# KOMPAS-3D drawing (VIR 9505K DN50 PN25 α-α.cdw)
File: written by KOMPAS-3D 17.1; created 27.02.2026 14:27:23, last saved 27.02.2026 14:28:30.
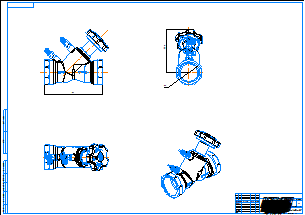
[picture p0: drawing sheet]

Sheet 1: A1, landscape

Title block, sheet 1: name: VIR 9505K DN50 / PN25 р-р; material: Внимание! Данный продукт является объектом авторского права ООО «Торговый Дом АДЛ». / Запрещается изменение, копирование, распространение / (в том числе путем копирования на другие сайты и ресурсы в Интернете) / или любое иное использование информации и объектов без предварительного / согласия правообладателя (ООО «Торговый Дом АДЛ»).; sheets: 1; organisation: ООО "Торговый дом АДЛ"; sheet format: A1

Views: Вид 1, Спереди, Проекционный вид 2, Проекционный вид 3, Вид 4, Изометрия
Referenced files in C:\Users\mipv\Desktop\VIR 9505K STP формат\: VIR 9505K DN50 PN25 р-р.m3d
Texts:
  adm
Dimensions and other numbers on the sheet: 118,5; 161; 1:1; 1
